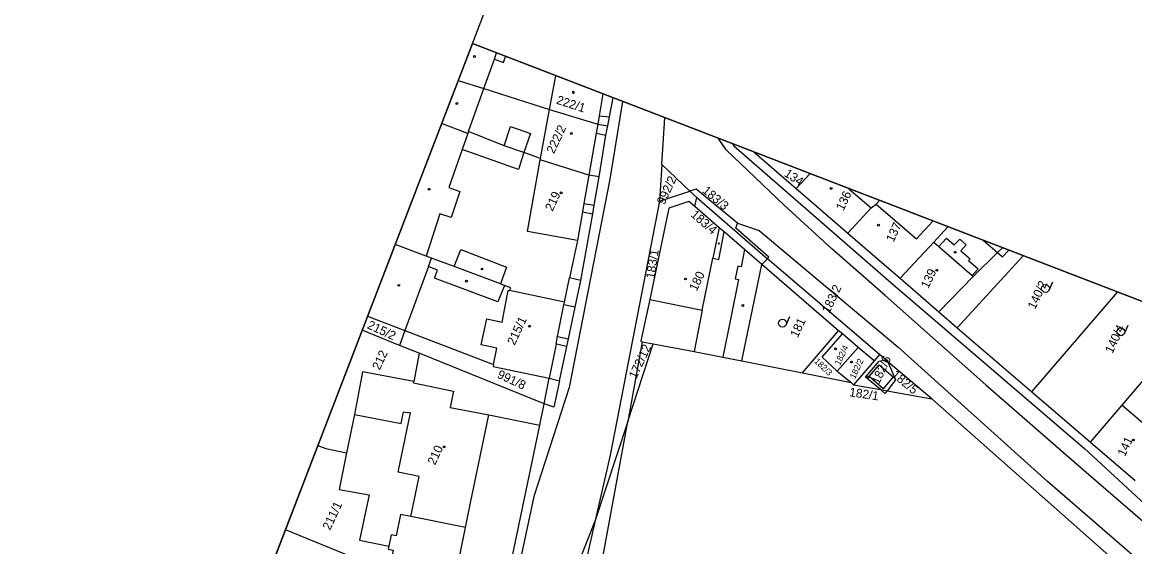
# Model space of a CAD drawing. Extents: x -755344 to -754413, y -1162670 to -1161477.
# Drawn here: x -755129.3 to -754914.5, y -1161770.1 to -1161668.9 of the extents above; entities that cross this region are included whole.
import ezdxf

# ---------------------------------------------------------------- set-up
doc = ezdxf.new("R2010")
doc.units = 0
for name, color, linetype in [('Formát', 7, 'Continuous'), ('Vrstva 55', 7, 'Continuous'), ('Vrstva 56', 7, 'Continuous'), ('Vrstva 57', 7, 'Continuous'), ('Vrstva 58', 7, 'Continuous'), ('Vrstva 59', 7, 'Continuous')]:
    doc.layers.add(name, color=color, linetype=linetype)

msp = doc.modelspace()

# ---------------------------------------------------------------- linework, layer by layer
at = {"layer": 'Formát'}
for q in [(-754966.95, -1161477.04), (-755344.08, -1162456.97), (-755344.08, -1162456.97)]:
    msp.add_line((-755042.37, -1161673.02), q, dxfattribs=at)
msp.add_lwpolyline([(-754488.01, -1161886.37), (-754789.71, -1162670.32), (-755344.08, -1162456.97), (-755042.37, -1161673.02)], close=True, dxfattribs=at)
for points in [[(-755344.08, -1162456.97), (-754789.71, -1162670.32), (-754488.01, -1161886.37), (-755042.37, -1161673.02)], [(-755344.08, -1162456.97), (-754789.71, -1162670.32), (-754488.01, -1161886.37), (-755042.37, -1161673.02)], [(-754789.71, -1162670.32), (-754488.01, -1161886.37), (-755042.37, -1161673.02), (-755344.08, -1162456.97)]]:
    msp.add_lwpolyline(points, dxfattribs=at)
at = {"layer": 'Vrstva 55'}
for p, q in [((-754987.94, -1161693.97), (-754979.83, -1161700.97)), ((-755005.78, -1161696.36), (-755006.24, -1161703.45)), ((-755000.37, -1161701.51), (-755005.78, -1161696.36)), ((-755006.24, -1161703.45), (-755000.37, -1161701.51)), ((-754999.07, -1161702.74), (-755000.37, -1161701.51)), ((-754979.83, -1161700.97), (-754969.9, -1161709.58)), ((-754999.42, -1161704.46), (-754999.07, -1161702.74)), ((-754999.07, -1161702.74), (-754985.41, -1161714.55)), ((-754985.41, -1161714.55), (-754986.49, -1161715.65)), ((-754963.8, -1161733.02), (-754985.41, -1161714.55)), ((-754948.77, -1161727.83), (-754936.01, -1161713.96)), ((-754990.38, -1161734.22), (-754986.49, -1161715.65)), ((-754971.69, -1161728.46), (-754986.49, -1161715.65)), ((-754959.79, -1161718.27), (-754952.34, -1161724.76)), ((-754934.36, -1161740.2), (-754917.81, -1161720.96)), ((-754952.34, -1161724.76), (-754948.77, -1161727.83)), ((-754948.77, -1161727.83), (-754934.36, -1161740.2)), ((-754978.64, -1161736.57), (-754971.69, -1161728.46)), ((-754970.94, -1161729.03), (-754971.69, -1161728.46)), ((-754967.88, -1161731.67), (-754970.94, -1161729.03)), ((-755009.58, -1161730.57), (-755012.38, -1161745.91)), ((-755012.38, -1161745.91), (-755007.48, -1161730.96)), ((-755009.58, -1161730.57), (-755007.48, -1161730.96)), ((-754967.88, -1161731.67), (-754971.93, -1161736.25)), ((-754964.78, -1161734.24), (-754967.88, -1161731.67)), ((-755028.51, -1161742.5), (-755052.64, -1161732.78)), ((-754990.38, -1161734.22), (-754978.64, -1161736.57)), ((-754964.78, -1161734.24), (-754968.79, -1161738.86)), ((-754963.8, -1161733.02), (-754964.78, -1161734.24)), ((-754962.57, -1161734.06), (-754963.8, -1161733.02)), ((-754962.13, -1161734.44), (-754962.57, -1161734.06)), ((-754953.69, -1161741.58), (-754962.13, -1161734.44)), ((-754978.64, -1161736.57), (-754969.27, -1161738.43)), ((-754971.93, -1161736.25), (-754969.27, -1161738.43)), ((-755028.51, -1161742.5), (-755027.52, -1161737.6)), ((-755027.52, -1161737.6), (-755025.54, -1161738.11)), ((-754969.27, -1161738.43), (-754968.79, -1161738.86)), ((-754968.79, -1161738.86), (-754963.61, -1161739.79)), ((-754963.61, -1161739.79), (-754962.32, -1161740.03)), ((-754962.32, -1161740.03), (-754953.69, -1161741.58)), ((-754934.36, -1161740.2), (-754923.04, -1161749.93)), ((-755029.37, -1161746.66), (-755028.51, -1161742.5)), ((-755036.5, -1161780.73), (-755029.37, -1161746.66)), ((-755018.69, -1161780.44), (-755012.38, -1161745.91)), ((-755012.38, -1161745.91), (-755018.66, -1161765.05)), ((-754923.04, -1161749.93), (-754914.4, -1161757.3)), ((-755018.66, -1161765.05), (-755023.99, -1161778.44)), ((-755063.99, -1161772.75), (-755078.47, -1161766.81))]:
    msp.add_line(p, q, dxfattribs=at)
for points in [[(-755045.1, -1161680.12), (-755040.15, -1161681.69), (-755027.46, -1161685.72), (-755018.17, -1161688.54), (-755016.23, -1161688.9)], [(-755013.38, -1161684.18), (-755015.84, -1161699.17), (-755023.66, -1161739.37), (-755030.54, -1161760.43), (-755032.94, -1161771.83), (-755032.59, -1161783.86), (-755042.91, -1161835.1), (-755052.57, -1161882.7), (-755054.53, -1161882.87), (-755056.71, -1161887.12)], [(-755016.23, -1161688.9), (-755015.87, -1161687.12), (-755015.22, -1161683.47)], [(-755017.87, -1161698.7), (-755019.88, -1161698.39), (-755029.28, -1161695.42), (-755029.22, -1161695.16), (-755032.44, -1161694.05), (-755036.25, -1161692.73), (-755043.15, -1161689.97), (-755043.28, -1161690.35), (-755048.31, -1161688.46)], [(-755017.87, -1161698.7), (-755016.58, -1161690.66), (-755016.23, -1161688.9)], [(-755005.78, -1161696.36), (-755005.19, -1161687.33)], [(-754992.13, -1161692.36), (-754991.87, -1161692.75), (-754961.05, -1161719.56), (-754924.16, -1161751.14), (-754883.24, -1161788.9), (-754859.67, -1161809.81)], [(-755022.5, -1161723.9), (-755021.42, -1161718.75), (-755019.14, -1161705.86), (-755018.84, -1161704.19), (-755017.87, -1161698.7)], [(-754979.83, -1161700.97), (-754977.18, -1161698.11)], [(-754985.41, -1161714.55), (-754985.11, -1161714.24), (-754991.52, -1161708.65), (-754991.16, -1161707.68), (-754999.16, -1161701.11), (-755000.37, -1161701.51)], [(-755006.24, -1161703.45), (-755015.79, -1161752.42), (-755018.66, -1161765.05)], [(-754999.42, -1161704.46), (-755000.57, -1161703.47), (-755004.47, -1161704.76), (-755008.12, -1161722.39), (-755009.83, -1161730.4), (-755009.58, -1161730.57)], [(-754969.9, -1161709.58), (-754965.35, -1161704.72), (-754964.42, -1161704), (-754963.75, -1161703.28)], [(-754986.49, -1161715.65), (-754989.82, -1161712.77), (-754993.77, -1161709.36), (-754994.71, -1161708.54), (-754999.42, -1161704.46)], [(-754959.79, -1161718.27), (-754953.28, -1161711.36), (-754950.58, -1161708.35)], [(-754969.9, -1161709.58), (-754963.77, -1161714.86), (-754959.79, -1161718.27)], [(-755022.5, -1161723.9), (-755024.69, -1161723.43), (-755024.58, -1161722.88), (-755035.2, -1161720.68), (-755034.98, -1161720.14), (-755036.15, -1161719.7), (-755036.96, -1161719.39), (-755045.89, -1161716.05), (-755050.24, -1161714.41), (-755051.31, -1161714.01), (-755057.28, -1161711.76)], [(-754952.34, -1161724.76), (-754945.68, -1161717.94), (-754941, -1161713.33), (-754940.05, -1161712.4)], [(-755062.62, -1161725.64), (-755055.4, -1161728.39), (-755038.3, -1161734.91)], [(-755025.54, -1161738.11), (-755024.12, -1161731.47), (-755023.8, -1161729.98), (-755022.5, -1161723.9)], [(-754923.04, -1161749.93), (-754916.92, -1161742.76), (-754903.14, -1161726.61)], [(-755052.64, -1161732.78), (-755056.45, -1161731.25), (-755063.65, -1161728.31)], [(-754971.93, -1161736.25), (-754974.81, -1161733.49), (-754970.94, -1161729.03)], [(-755007.48, -1161730.96), (-754999.54, -1161732.44), (-754994.03, -1161733.53), (-754990.38, -1161734.22)], [(-755052.64, -1161732.78), (-755053.71, -1161738.24), (-755063.56, -1161736.32), (-755065.16, -1161744.58), (-755066.7, -1161752.01)], [(-754963.61, -1161739.79), (-754966.45, -1161737.38), (-754963.82, -1161734.29), (-754962.57, -1161734.06)], [(-754962.13, -1161734.44), (-754960.7, -1161737.88), (-754962.32, -1161740.03)], [(-755038.3, -1161734.91), (-755038.38, -1161735.3), (-755027.52, -1161737.6)], [(-755025.54, -1161738.11), (-755026.62, -1161743.19), (-755028.51, -1161742.5)], [(-754790.69, -1161920.17), (-754823.33, -1161865.1), (-754831.37, -1161854.01), (-754842.43, -1161841.79), (-754855.01, -1161828.87), (-754953.69, -1161741.58)], [(-755066.7, -1161752.01), (-755068.08, -1161759.03), (-755062.31, -1161760.06), (-755064.15, -1161768.86), (-755058.51, -1161770.01), (-755058.63, -1161770.54), (-755057.66, -1161770.75), (-755058.23, -1161773.52), (-755045.73, -1161776.2), (-755043.71, -1161766.41), (-755042.79, -1161761.96), (-755039.2, -1161744.67), (-755029.37, -1161746.66)], [(-755072.22, -1161750.59), (-755070.67, -1161751.12), (-755066.7, -1161752.01)]]:
    msp.add_lwpolyline(points, dxfattribs=at)
at = {"layer": 'Vrstva 56'}
for p, q in [((-755040.15, -1161681.69), (-755038.11, -1161676.04)), ((-755038.11, -1161676.04), (-755037.71, -1161674.82)), ((-755038.11, -1161676.04), (-755036.35, -1161676.66)), ((-755036.35, -1161676.66), (-755035.95, -1161675.52)), ((-755035.95, -1161675.52), (-755035.73, -1161675.58)), ((-755027.46, -1161685.72), (-755026.28, -1161679.22)), ((-755043.15, -1161689.97), (-755040.15, -1161681.69)), ((-755017.16, -1161682.73), (-755017.89, -1161686.93)), ((-755029.22, -1161695.16), (-755027.46, -1161685.72)), ((-755017.89, -1161686.93), (-755018.17, -1161688.54)), ((-755017.89, -1161686.93), (-755015.87, -1161687.12)), ((-755036.25, -1161692.73), (-755035.01, -1161689.04)), ((-755035.01, -1161689.04), (-755031.17, -1161690.35)), ((-755018.17, -1161688.54), (-755018.47, -1161690.29)), ((-755043.28, -1161690.35), (-755044.33, -1161693.43)), ((-755031.17, -1161690.35), (-755032.44, -1161694.05)), ((-755018.47, -1161690.29), (-755019.88, -1161698.39)), ((-755018.47, -1161690.29), (-755016.58, -1161690.66)), ((-754993.37, -1161693.51), (-754994.94, -1161691.28)), ((-755044.33, -1161693.43), (-755046.94, -1161700.81)), ((-755033.47, -1161697.33), (-755044.33, -1161693.43)), ((-754982.15, -1161704.19), (-754993.37, -1161693.51)), ((-755032.44, -1161694.05), (-755033.47, -1161697.33)), ((-755031.76, -1161709.25), (-755029.28, -1161695.42)), ((-755019.88, -1161698.39), (-755020.83, -1161703.89)), ((-755046.94, -1161700.81), (-755044.77, -1161701.56)), ((-755044.77, -1161701.56), (-755046.5, -1161706.59)), ((-754969.66, -1161701.01), (-754965.35, -1161704.72)), ((-755020.83, -1161703.89), (-755021.11, -1161705.47)), ((-755020.83, -1161703.89), (-755018.84, -1161704.19)), ((-754972.97, -1161712.61), (-754982.15, -1161704.19)), ((-754964.42, -1161704), (-754956.65, -1161710.67)), ((-755048.66, -1161705.85), (-755051.31, -1161714.01)), ((-755046.5, -1161706.59), (-755048.66, -1161705.85)), ((-755021.11, -1161705.47), (-755022.06, -1161710.98)), ((-755021.11, -1161705.47), (-755019.14, -1161705.86)), ((-754994.71, -1161708.54), (-754995.92, -1161714.4)), ((-754991.16, -1161707.68), (-754987.03, -1161709.11)), ((-754953.45, -1161707.25), (-754956.65, -1161710.67)), ((-755022.06, -1161710.98), (-755031.76, -1161709.25)), ((-754994.8, -1161714.66), (-754993.77, -1161709.36)), ((-754987.03, -1161709.11), (-754960.25, -1161731.5)), ((-754952.29, -1161712.19), (-754950.83, -1161710.56)), ((-754950.83, -1161710.56), (-754949.33, -1161711.87)), ((-754949.33, -1161711.87), (-754948.26, -1161710.72)), ((-754948.26, -1161710.72), (-754947.03, -1161711.83)), ((-755045.89, -1161716.05), (-755044.58, -1161712.76)), ((-755044.58, -1161712.76), (-755035.76, -1161716.18)), ((-755022.06, -1161710.98), (-755023.6, -1161718.23)), ((-754989.82, -1161712.77), (-754990.49, -1161716.08)), ((-754962.66, -1161721.63), (-754972.97, -1161712.61)), ((-754953.28, -1161711.36), (-754952.29, -1161712.19)), ((-754952.29, -1161712.19), (-754945.87, -1161717.78)), ((-754947.03, -1161711.83), (-754948.04, -1161712.99)), ((-754948.04, -1161712.99), (-754946.27, -1161714.52)), ((-754943.67, -1161711.01), (-754941, -1161713.33)), ((-754940.01, -1161714.16), (-754938.83, -1161712.87)), ((-755050.84, -1161716.03), (-755050.24, -1161714.41)), ((-754998, -1161724.47), (-754995.92, -1161714.4)), ((-754995.92, -1161714.4), (-754994.8, -1161714.66)), ((-754946.27, -1161714.52), (-754946.57, -1161714.86)), ((-754946.57, -1161714.86), (-754944.75, -1161716.46)), ((-754941, -1161713.33), (-754940.01, -1161714.16)), ((-755050.84, -1161716.03), (-755055.4, -1161728.39)), ((-755049.08, -1161716.71), (-755050.84, -1161716.03)), ((-755049.66, -1161718.28), (-755049.08, -1161716.71)), ((-755035.76, -1161716.18), (-755036.96, -1161719.39)), ((-754991.11, -1161715.96), (-754991.62, -1161718.4)), ((-754990.49, -1161716.08), (-754991.11, -1161715.96)), ((-754944.75, -1161716.46), (-754945.87, -1161717.78)), ((-755037.48, -1161722.82), (-755049.66, -1161718.28)), ((-755024.58, -1161722.88), (-755023.6, -1161718.23)), ((-755021.42, -1161718.75), (-755023.6, -1161718.23)), ((-754990.99, -1161718.52), (-754994.03, -1161733.53)), ((-754991.62, -1161718.4), (-754990.99, -1161718.52)), ((-754945.87, -1161717.78), (-754945.68, -1161717.94)), ((-755036.15, -1161719.7), (-755037.48, -1161722.82)), ((-755036.61, -1161726.74), (-755035.47, -1161720.63)), ((-755035.47, -1161720.63), (-755035.2, -1161720.68)), ((-754962.66, -1161721.63), (-754943.25, -1161738.89)), ((-755025.91, -1161729.53), (-755024.69, -1161723.43)), ((-755008.12, -1161722.39), (-754998, -1161724.47)), ((-754998, -1161724.47), (-754999.54, -1161732.44)), ((-755040.69, -1161731.15), (-755039.61, -1161726.11)), ((-755039.61, -1161726.11), (-755036.61, -1161726.74)), ((-755055.4, -1161728.39), (-755056.45, -1161731.25)), ((-755026.21, -1161731.04), (-755025.91, -1161729.53)), ((-755025.91, -1161729.53), (-755023.8, -1161729.98)), ((-755037.65, -1161731.78), (-755040.69, -1161731.15)), ((-755038.3, -1161734.91), (-755037.65, -1161731.78)), ((-755026.21, -1161731.04), (-755027.52, -1161737.6)), ((-755024.12, -1161731.47), (-755026.21, -1161731.04)), ((-754931.36, -1161757.54), (-754960.25, -1161731.5)), ((-754962.57, -1161734.06), (-754962.3, -1161734.02)), ((-754962.3, -1161734.02), (-754962.13, -1161734.44)), ((-754965.75, -1161737.28), (-754963.83, -1161735.02)), ((-754963.83, -1161735.02), (-754961.12, -1161737.33)), ((-755053.75, -1161738.45), (-755053.71, -1161738.24)), ((-755053.75, -1161738.45), (-755046.02, -1161740.06)), ((-754963.05, -1161739.61), (-754965.75, -1161737.28)), ((-754961.12, -1161737.33), (-754963.05, -1161739.61)), ((-755046.02, -1161740.06), (-755046.67, -1161743.21)), ((-754962.71, -1161740.56), (-754963.61, -1161739.79)), ((-754962.32, -1161740.03), (-754962.71, -1161740.56)), ((-754943.25, -1161738.89), (-754926.26, -1161753.63)), ((-754916.92, -1161742.76), (-754911.23, -1161747.61)), ((-755065.16, -1161744.58), (-755056.13, -1161746.34)), ((-755056.71, -1161755.68), (-755054.35, -1161744.29)), ((-755056.13, -1161746.34), (-755055.66, -1161744.06)), ((-755055.66, -1161744.06), (-755054.87, -1161744.19)), ((-755054.35, -1161744.29), (-755054.87, -1161744.19)), ((-755046.67, -1161743.21), (-755039.2, -1161744.67)), ((-754926.26, -1161753.63), (-754883.79, -1161790.36)), ((-755052.67, -1161756.55), (-755056.71, -1161755.68)), ((-755053.42, -1161760.28), (-755052.67, -1161756.55)), ((-754908.58, -1161777.13), (-754931.36, -1161757.54)), ((-755054.23, -1161764.27), (-755053.42, -1161760.28)), ((-755056.23, -1161763.86), (-755057.08, -1161767.98)), ((-755054.23, -1161764.27), (-755056.23, -1161763.86)), ((-755043.71, -1161766.41), (-755054.23, -1161764.27)), ((-755018.66, -1161765.05), (-755021.88, -1161779.23)), ((-755058.05, -1161767.78), (-755058.51, -1161770.01)), ((-755057.08, -1161767.98), (-755058.05, -1161767.78))]:
    msp.add_line(p, q, dxfattribs=at)
at = {"layer": 'Vrstva 58'}
for p, q in [((-754931.04, -1161720.58), (-754930.3, -1161719)), ((-754981.82, -1161727.28), (-754981.08, -1161725.7)), ((-754916.5, -1161728.95), (-754915.76, -1161727.37))]:
    msp.add_line(p, q, dxfattribs=at)
for centre in [(-754931.72, -1161720.27), (-754982.5, -1161726.97), (-754917.18, -1161728.64)]:
    msp.add_circle(centre, 0.75, dxfattribs=at)
at = {"layer": 'Vrstva 59'}
msp.add_line((-755022.71, -1161682.34), (-755022.95, -1161682.24), dxfattribs=at)
for centre, radius in [((-755041.96, -1161675.51), 0.175), ((-755045.36, -1161684.58), 0.175), ((-755023.27, -1161690.35), 0.175), ((-755050.72, -1161701.12), 0.175), ((-755025.24, -1161701.81), 0.175), ((-754973.1, -1161700.96), 0.175), ((-754963.96, -1161708.06), 0.175), ((-754994.8, -1161711.58), 0.117), ((-754949.15, -1161713.28), 0.175), ((-755040.52, -1161716.51), 0.175), ((-754952.7, -1161716.76), 0.175), ((-755056.6, -1161719.66), 0.175), ((-755043.53, -1161718.87), 0.175), ((-755001.25, -1161718.44), 0.175), ((-754990.18, -1161723.56), 0.175), ((-755031.34, -1161727.56), 0.175), ((-754972.24, -1161731.92), 0.175), ((-754969.18, -1161734.46), 0.175), ((-754965.91, -1161737.34), 0.175), ((-754914.75, -1161749.5), 0.175), ((-755047.84, -1161750.84), 0.175)]:
    msp.add_circle(centre, radius, dxfattribs=at)
msp.add_arc((-755022.87, -1161682.4), 0.175, 118.333, 19.5683, dxfattribs=at)

# ---------------------------------------------------------------- texts
at = {"layer": 'Vrstva 57'}
for s, height, rotation, p in [('222/1', 1.7, 342.0551, (-755026.29, -1161684.58)), ('222/2', 1.7, 65, (-755026.62, -1161694.39)), ('134', 1.7, 326.5771, (-754982.33, -1161698.46)), ('992/2', 1.7, 65, (-755005.31, -1161704.24)), ('219', 1.7, 65, (-755026.9, -1161705.49)), ('183/3', 1.7, 319.5822, (-754998.12, -1161701.6)), ('136', 1.7, 65, (-754970.73, -1161705.39)), ('183/4', 1.7, 318.8839, (-755000.35, -1161706.22)), ('137', 1.7, 65, (-754961.07, -1161711.47)), ('183/1', 1.7, 81.3851, (-755007.23, -1161718.48)), ('180', 1.7, 65, (-754999.06, -1161720.91)), ('139', 1.7, 65, (-754954.34, -1161720.41)), ('140/2', 1.7, 65, (-754933.73, -1161724.43)), ('183/2', 1.7, 65, (-754973.46, -1161725.21)), ('215/1', 1.7, 65, (-755034.21, -1161731.35)), ('215/2', 1.7, 335, (-755062.82, -1161727.89)), ('181', 1.7, 65, (-754979.57, -1161729.89)), ('140/4', 1.7, 65, (-754918.79, -1161732.93)), ('212', 1.7, 65, (-755060.28, -1161736.13)), ('172/12', 1.7, 65, (-755010.74, -1161737.84)), ('182/4', 1.2, 65, (-754971.42, -1161735.2)), ('182/3', 1.2, 316.5042, (-754976.47, -1161734.44)), ('182/2', 1.2, 65, (-754968.5, -1161737.8)), ('182/6', 1.7, 65, (-754963.88, -1161738.9)), ('991/8', 1.7, 335, (-755037.72, -1161737.43)), ('182/5', 1.7, 320.0035, (-754961.57, -1161737.14)), ('182/1', 1.7, 351.505, (-754969.68, -1161741.04)), ('141', 1.7, 65, (-754916.39, -1161752.81)), ('210', 1.7, 65, (-755049.59, -1161754.47)), ('211/1', 1.7, 65, (-755069.86, -1161767.03))]:
    msp.add_text(s, height=height, rotation=rotation, dxfattribs=at).set_placement(p)

doc.saveas('drawing.dxf')
